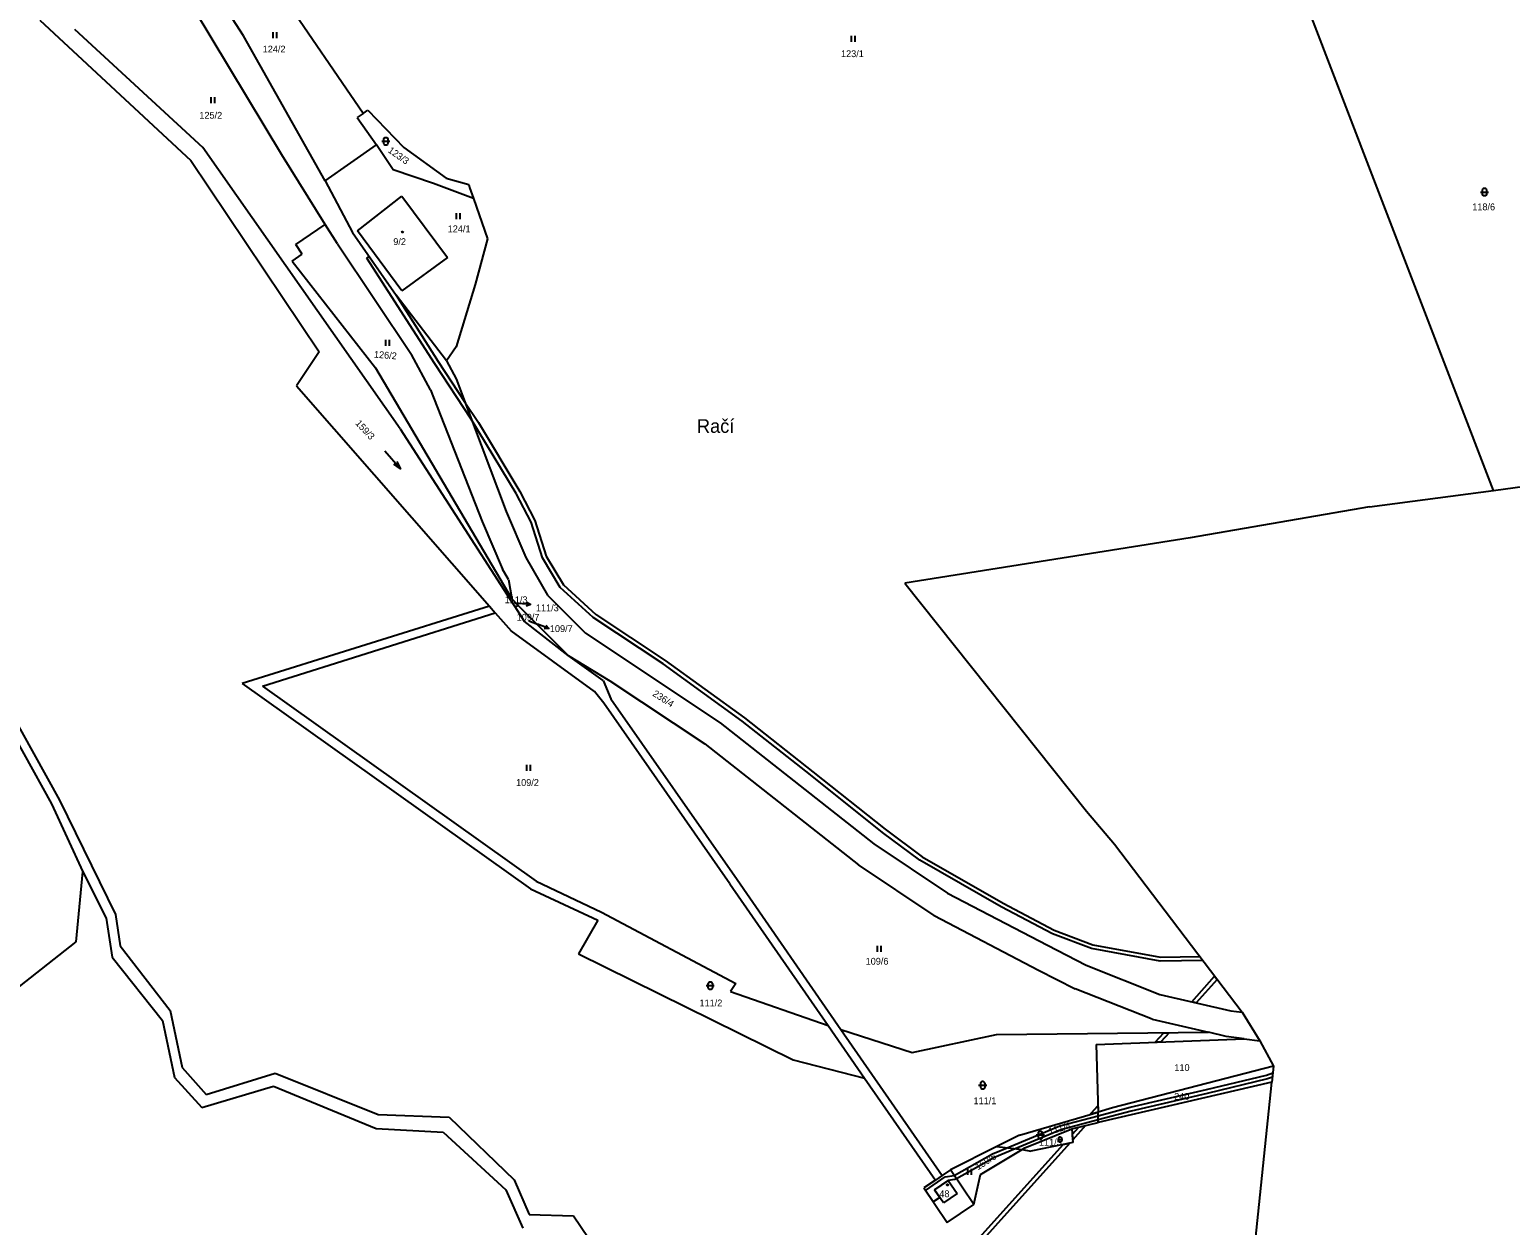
# Model space of a CAD drawing. Extents: x -811039 to -805820, y -1161436 to -1155864.
# Drawn here: x -809432.5 to -809063.2, y -1160199.3 to -1159901.1 of the extents above; entities that cross this region are included whole.
import ezdxf

# ---------------------------------------------------------------- set-up
doc = ezdxf.new("R2010")
doc.units = 0
for name, color, linetype in [('Default', 7, 'Continuous'), ('Hranice kat_území', 7, 'Continuous'), ('Hranice parcel', 7, 'Continuous'), ('Parcelní čísla', 7, 'Continuous'), ('Pop  PČ popisy', 7, 'Continuous'), ('Vnitřní kresba', 7, 'Continuous'), ('Věcná břemena k části', 7, 'Continuous'), ('Značky budov', 7, 'Continuous'), ('Značky kultur', 7, 'Continuous')]:
    doc.layers.add(name, color=color, linetype=linetype)

# ---------------------------------------------------------------- blocks, each defined once
blk = doc.blocks.new('306')
at = {"layer": 'Default'}
for p, q in [((-0.5, 1.5), (-0.5, 0)), ((0.5, 0), (0.5, 1.5))]:
    blk.add_line(p, q, dxfattribs=at)
blk = doc.blocks.new('316')
at = {"layer": 'Default'}
for points in [[(-1, 1), (0.27, 1), (1, 1)], [(-0.5, 1.5), (-0.4, 1.79), (-0.15, 1.97), (0.16, 1.97), (0.41, 1.79), (0.51, 1.5), (0.51, 0.5), (0.41, 0.21), (0.16, 0.03), (-0.15, 0.03), (-0.4, 0.21), (-0.5, 0.5), (-0.5, 1.5)]]:
    blk.add_lwpolyline(points, dxfattribs=at)
blk = doc.blocks.new('802')
at = {"layer": 'Default'}
blk.add_line((-3, 0), (3, 0), dxfattribs=at)
blk.add_lwpolyline([(1, 0.5), (3, 0), (1, -0.5)], dxfattribs=at)
blk = doc.blocks.new('10292')
at = {"layer": 'Default'}
blk.add_line((0, 3), (0, 0), dxfattribs=at)
blk.add_lwpolyline([(-0.5, 2), (0, 3), (0.5, 2)], dxfattribs=at)
blk = doc.blocks.new('402')
at = {"layer": 'Default'}
blk.add_lwpolyline([(0.09, 0.15), (0.18, 0), (0.09, -0.15), (-0.09, -0.15), (-0.18, 0), (-0.09, 0.15), (0.09, 0.15)], dxfattribs=at)

msp = doc.modelspace()

# ---------------------------------------------------------------- linework, layer by layer
at = {"layer": 'Hranice kat_území'}
for p, q in [((-809067.45, -1160016.03), (-809030.93, -1160011.2)), ((-809098.39, -1160020.11), (-809067.45, -1160016.03)), ((-809098.39, -1160020.11), (-809143.12, -1160027.89)), ((-809143.12, -1160027.89), (-809214.22, -1160039.19)), ((-809214.22, -1160039.19), (-809168.92, -1160096.04)), ((-809168.92, -1160096.04), (-809161.97, -1160104.28)), ((-809161.97, -1160104.28), (-809130.15, -1160146.17)), ((-809130.15, -1160146.17), (-809125.72, -1160153.31)), ((-809125.72, -1160153.31), (-809122.3, -1160159.64)), ((-809122.3, -1160159.64), (-809122.72, -1160163.6)), ((-809127.49, -1160209.16), (-809122.72, -1160163.6))]:
    msp.add_line(p, q, dxfattribs=at)
at = {"layer": 'Hranice parcel'}
for p, q in [((-809067.45, -1160016.03), (-809126.06, -1159863.64)), ((-809379.2, -1159902.71), (-809396.36, -1159875.89)), ((-809349.31, -1159922.05), (-809378.21, -1159879.76)), ((-809429.99, -1159898.77), (-809392.27, -1159933.76)), ((-809369.63, -1159932.33), (-809391.4, -1159896.21)), ((-809421.33, -1159901.04), (-809389.33, -1159930.55)), ((-809358.79, -1159938.85), (-809379.2, -1159902.71)), ((-809349.31, -1159922.05), (-809350.84, -1159923.07)), ((-809350.84, -1159923.07), (-809346, -1159929.89)), ((-809349.31, -1159922.05), (-809348.14, -1159921.26)), ((-809348.14, -1159921.26), (-809339.21, -1159930.5)), ((-809340.11, -1160000.67), (-809389.33, -1159930.55)), ((-809358.79, -1159938.85), (-809346, -1159929.89)), ((-809341.81, -1159936.08), (-809346, -1159929.89)), ((-809339.21, -1159930.5), (-809328.66, -1159938.21)), ((-809392.27, -1159933.76), (-809360.3, -1159981.53)), ((-809358.78, -1159949.7), (-809369.63, -1159932.33)), ((-809358.79, -1159938.85), (-809351.99, -1159951.73)), ((-809331.78, -1159939.48), (-809341.81, -1159936.08)), ((-809328.66, -1159938.21), (-809322.97, -1159939.79)), ((-809350.74, -1159951.29), (-809339.66, -1159942.68)), ((-809339.66, -1159942.68), (-809328.31, -1159957.96)), ((-809321.84, -1159943.27), (-809331.78, -1159939.48)), ((-809322.97, -1159939.79), (-809322.8, -1159940.55)), ((-809322.8, -1159940.55), (-809321.84, -1159943.27)), ((-809321.84, -1159943.27), (-809318.31, -1159953.35)), ((-809366.16, -1159954.76), (-809358.78, -1159949.7)), ((-809355.76, -1159954.53), (-809358.78, -1159949.7)), ((-809351.99, -1159951.73), (-809341.13, -1159967.36)), ((-809339.69, -1159966.3), (-809350.74, -1159951.29)), ((-809318.31, -1159953.35), (-809321.41, -1159964.66)), ((-809367.06, -1159958.87), (-809364.58, -1159957.1)), ((-809364.58, -1159957.1), (-809366.16, -1159954.76)), ((-809355.76, -1159954.53), (-809337.31, -1159982.17)), ((-809367.06, -1159958.87), (-809346.28, -1159985.44)), ((-809328.31, -1159957.96), (-809339.69, -1159966.3)), ((-809321.41, -1159964.66), (-809326.16, -1159980.21)), ((-809328.54, -1159983.73), (-809341.13, -1159967.36)), ((-809360.3, -1159981.53), (-809365.93, -1159989.95)), ((-809332.58, -1159990.98), (-809337.31, -1159982.17)), ((-809326.16, -1159980.21), (-809328.54, -1159983.73)), ((-809328.54, -1159983.73), (-809326.14, -1159988.22)), ((-809346.28, -1159985.44), (-809312.23, -1160043.12)), ((-809365.93, -1159989.95), (-809317.85, -1160044.93)), ((-809332.58, -1159990.98), (-809319.69, -1160023.76)), ((-809326.14, -1159988.22), (-809313.66, -1160021.34)), ((-809340.11, -1160000.67), (-809312.66, -1160043.26)), ((-809319.69, -1160023.76), (-809314.59, -1160035.71)), ((-809313.66, -1160021.34), (-809308.76, -1160032.8)), ((-809308.76, -1160032.8), (-809303.34, -1160042.21)), ((-809313.12, -1160038.25), (-809314.59, -1160035.71)), ((-809313.12, -1160038.25), (-809312.23, -1160043.12)), ((-809303.34, -1160042.21), (-809293.85, -1160051.68)), ((-809454.13, -1160045.44), (-809427.07, -1160094.22)), ((-809451.73, -1160045.3), (-809425.03, -1160093.32)), ((-809317.85, -1160044.93), (-809379.47, -1160064.19)), ((-809317.85, -1160044.93), (-809316.42, -1160046.57)), ((-809312.23, -1160043.12), (-809312.66, -1160043.26)), ((-809312.66, -1160043.26), (-809311.54, -1160045)), ((-809312.23, -1160043.12), (-809310.66, -1160044.72)), ((-809311.54, -1160045), (-809310.66, -1160044.72)), ((-809311.54, -1160045), (-809309.2, -1160048.63)), ((-809310.66, -1160044.72), (-809298.21, -1160057.19)), ((-809374.46, -1160064.84), (-809316.42, -1160046.57)), ((-809316.42, -1160046.57), (-809312.45, -1160051.1)), ((-809298.21, -1160057.19), (-809309.2, -1160048.63)), ((-809291.62, -1160066.18), (-809312.45, -1160051.1)), ((-809293.85, -1160051.68), (-809260.32, -1160073.99)), ((-809289.45, -1160063.43), (-809298.21, -1160057.19)), ((-809298.21, -1160057.19), (-809287.8, -1160063.51)), ((-809379.47, -1160064.19), (-809307.59, -1160115.43)), ((-809374.46, -1160064.84), (-809306.19, -1160113.52)), ((-809289.45, -1160063.43), (-809287.56, -1160068.04)), ((-809287.8, -1160063.51), (-809264.14, -1160079.26)), ((-809289.32, -1160069.08), (-809291.62, -1160066.18)), ((-809287.56, -1160068.04), (-809256.06, -1160113.07)), ((-809257.89, -1160114.17), (-809289.32, -1160069.08)), ((-809260.32, -1160073.99), (-809221.98, -1160104.19)), ((-809264.14, -1160079.26), (-809225.8, -1160109.45)), ((-809427.07, -1160094.22), (-809419.25, -1160111.18)), ((-809425.03, -1160093.32), (-809411.06, -1160121.78)), ((-809221.98, -1160104.19), (-809203.63, -1160116.46)), ((-809420.88, -1160128.61), (-809419.25, -1160111.18)), ((-809419.25, -1160111.18), (-809413.46, -1160122.7)), ((-809206.95, -1160122.06), (-809225.8, -1160109.45)), ((-809307.59, -1160115.43), (-809290.84, -1160123.22)), ((-809306.19, -1160113.52), (-809289.91, -1160121.2)), ((-809257.89, -1160114.17), (-809233.37, -1160149.5)), ((-809256.06, -1160113.07), (-809230.18, -1160150.48)), ((-809203.63, -1160116.46), (-809178.69, -1160129.43)), ((-809413.46, -1160122.7), (-809411.9, -1160132.48)), ((-809411.06, -1160121.78), (-809409.97, -1160129.58)), ((-809290.84, -1160123.22), (-809295.61, -1160131.62)), ((-809289.91, -1160121.2), (-809256.39, -1160139)), ((-809206.95, -1160122.06), (-809180.93, -1160135.68)), ((-809435.03, -1160139.74), (-809420.88, -1160128.61)), ((-809409.97, -1160129.58), (-809397.42, -1160145.71)), ((-809178.69, -1160129.43), (-809169.07, -1160134.44)), ((-809411.9, -1160132.48), (-809399.36, -1160148.23)), ((-809295.61, -1160131.62), (-809242.1, -1160158.08)), ((-809169.07, -1160134.44), (-809150.64, -1160141.71)), ((-809180.93, -1160135.68), (-809171.75, -1160140.37)), ((-809256.39, -1160139), (-809257.74, -1160141.04)), ((-809257.74, -1160141.04), (-809233.37, -1160149.5)), ((-809152.58, -1160147.93), (-809171.75, -1160140.37)), ((-809150.64, -1160141.71), (-809132.98, -1160145.8)), ((-809397.42, -1160145.71), (-809394.46, -1160159.95)), ((-809132.98, -1160145.8), (-809130.15, -1160146.17)), ((-809399.36, -1160148.23), (-809396.35, -1160162.42)), ((-809233.37, -1160149.5), (-809224.27, -1160162.61)), ((-809152.58, -1160147.93), (-809138.55, -1160151.18)), ((-809230.18, -1160150.48), (-809204.97, -1160186.92)), ((-809230.18, -1160150.48), (-809212.41, -1160156.18)), ((-809212.41, -1160156.18), (-809191.36, -1160151.76)), ((-809191.36, -1160151.76), (-809138.55, -1160151.18)), ((-809166.53, -1160154.18), (-809129.63, -1160152.79)), ((-809134.14, -1160152.2), (-809138.55, -1160151.18)), ((-809129.63, -1160152.79), (-809134.14, -1160152.2)), ((-809129.63, -1160152.79), (-809125.72, -1160153.31)), ((-809166.53, -1160154.18), (-809166.07, -1160171.09)), ((-809394.46, -1160159.95), (-809388.49, -1160166.65)), ((-809242.1, -1160158.08), (-809224.27, -1160162.61)), ((-809122.3, -1160159.64), (-809162.45, -1160170.03)), ((-809396.35, -1160162.42), (-809389.58, -1160169.92)), ((-809389.58, -1160169.92), (-809371.71, -1160164.62)), ((-809388.49, -1160166.65), (-809371.31, -1160161.36)), ((-809371.71, -1160164.62), (-809346.09, -1160175.15)), ((-809371.31, -1160161.36), (-809345.55, -1160171.68)), ((-809224.27, -1160162.61), (-809206.63, -1160188.04)), ((-809122.72, -1160163.6), (-809166, -1160173.7)), ((-809345.55, -1160171.68), (-809327.88, -1160172.36)), ((-809185.67, -1160176.82), (-809166.07, -1160171.09)), ((-809162.45, -1160170.03), (-809166.07, -1160171.09)), ((-809166, -1160173.7), (-809166.07, -1160171.09)), ((-809346.09, -1160175.15), (-809329.35, -1160176.05)), ((-809327.88, -1160172.36), (-809311.71, -1160187.99)), ((-809184.32, -1160180.02), (-809172.57, -1160175.23)), ((-809172.57, -1160175.23), (-809166, -1160173.7)), ((-809172.57, -1160175.23), (-809172.35, -1160178.68)), ((-809329.35, -1160176.05), (-809313.76, -1160190.44)), ((-809185.67, -1160176.82), (-809191.29, -1160179.65)), ((-809172.35, -1160178.68), (-809182.82, -1160180.81)), ((-809191.29, -1160179.65), (-809202.88, -1160185.49)), ((-809195.4, -1160186.64), (-809185.01, -1160180.43)), ((-809191.29, -1160179.65), (-809185.01, -1160180.43)), ((-809185.01, -1160180.43), (-809184.32, -1160180.02)), ((-809185.01, -1160180.43), (-809182.82, -1160180.81)), ((-809202.88, -1160185.49), (-809204.97, -1160186.92)), ((-809197.03, -1160194.09), (-809202.88, -1160185.49)), ((-809197.03, -1160194.09), (-809195.4, -1160186.64)), ((-809313.76, -1160190.44), (-809309.52, -1160200.03)), ((-809311.71, -1160187.99), (-809307.91, -1160196.57)), ((-809206.63, -1160188.04), (-809209.52, -1160190)), ((-809209.52, -1160190), (-809203.71, -1160198.62)), ((-809204.97, -1160186.92), (-809206.63, -1160188.04)), ((-809203.71, -1160198.62), (-809197.03, -1160194.09)), ((-809307.91, -1160196.57), (-809296.85, -1160196.95)), ((-809296.85, -1160196.95), (-809285.9, -1160213.07))]:
    msp.add_line(p, q, dxfattribs=at)
at = {"layer": 'Pop  PČ popisy'}
for p, q in [((-809311.56, -1160044.17), (-809310.63, -1160044.24)), ((-809307.99, -1160048.53), (-809305.85, -1160049.36))]:
    msp.add_line(p, q, dxfattribs=at)
at = {"layer": 'Vnitřní kresba'}
for p, q in [((-809206.86, -1160190.44), (-809203.43, -1160188.17)), ((-809204.64, -1160193.7), (-809206.86, -1160190.44)), ((-809203.43, -1160188.17), (-809201.24, -1160191.34)), ((-809201.24, -1160191.34), (-809204.64, -1160193.7))]:
    msp.add_line(p, q, dxfattribs=at)
at = {"layer": 'Věcná břemena k části'}
for p, q in [((-809348.44, -1159958.12), (-809347.85, -1159957.68)), ((-809347.85, -1159957.68), (-809341.13, -1159967.36)), ((-809331.5, -1159984.48), (-809348.44, -1159958.12)), ((-809341.13, -1159967.36), (-809330.66, -1159983.94)), ((-809322.36, -1159998.25), (-809331.5, -1159984.48)), ((-809330.66, -1159983.94), (-809323.94, -1159994.07)), ((-809323.94, -1159994.07), (-809320.61, -1159999.08)), ((-809311.14, -1160016.81), (-809322.36, -1159998.25)), ((-809320.61, -1159999.08), (-809310.26, -1160016.33)), ((-809307.42, -1160023.95), (-809311.14, -1160016.81)), ((-809310.26, -1160016.33), (-809306.5, -1160023.57)), ((-809304.59, -1160032.9), (-809307.42, -1160023.95)), ((-809306.5, -1160023.57), (-809303.67, -1160032.48)), ((-809300.19, -1160040.23), (-809304.59, -1160032.9)), ((-809303.67, -1160032.48), (-809299.41, -1160039.59)), ((-809291.96, -1160047.78), (-809300.19, -1160040.23)), ((-809299.41, -1160039.59), (-809291.34, -1160046.98)), ((-809274.55, -1160059.28), (-809291.96, -1160047.78)), ((-809291.34, -1160046.98), (-809273.99, -1160058.46)), ((-809254.8, -1160073.56), (-809274.55, -1160059.28)), ((-809273.99, -1160058.46), (-809254.2, -1160072.76)), ((-809237.79, -1160086.97), (-809254.8, -1160073.56)), ((-809254.2, -1160072.76), (-809237.17, -1160086.19)), ((-809219.79, -1160101.36), (-809237.79, -1160086.97)), ((-809237.17, -1160086.19), (-809219.19, -1160100.56)), ((-809210.49, -1160108.22), (-809219.79, -1160101.36)), ((-809219.19, -1160100.56), (-809209.95, -1160107.38)), ((-809190.25, -1160119.87), (-809210.49, -1160108.22)), ((-809209.95, -1160107.38), (-809189.77, -1160118.99)), ((-809177.44, -1160126.6), (-809190.25, -1160119.87)), ((-809189.77, -1160118.99), (-809177.02, -1160125.68)), ((-809167.69, -1160130.32), (-809177.44, -1160126.6)), ((-809177.02, -1160125.68), (-809167.41, -1160129.36)), ((-809150.59, -1160133.46), (-809167.69, -1160130.32)), ((-809167.41, -1160129.36), (-809150.51, -1160132.46)), ((-809139.95, -1160133.27), (-809150.59, -1160133.46)), ((-809150.51, -1160132.46), (-809140.7, -1160132.29)), ((-809139.04, -1160165.45), (-809124.06, -1160161.84)), ((-809123.78, -1160162.8), (-809138.82, -1160166.43)), ((-809124.06, -1160161.84), (-809122.47, -1160161.28)), ((-809122.59, -1160162.38), (-809123.78, -1160162.8)), ((-809158.06, -1160169.84), (-809139.04, -1160165.45)), ((-809138.82, -1160166.43), (-809157.82, -1160170.82)), ((-809175.63, -1160174.52), (-809166.05, -1160171.97)), ((-809166.05, -1160171.97), (-809158.06, -1160169.84)), ((-809157.82, -1160170.82), (-809166.02, -1160173)), ((-809188.74, -1160179.97), (-809175.63, -1160174.52)), ((-809175.31, -1160175.46), (-809186.74, -1160180.22)), ((-809166.02, -1160173), (-809175.31, -1160175.46)), ((-809201.96, -1160186.85), (-809192.36, -1160181.47)), ((-809191.92, -1160182.37), (-809201.39, -1160187.68)), ((-809192.36, -1160181.47), (-809188.74, -1160179.97)), ((-809186.74, -1160180.22), (-809191.92, -1160182.37)), ((-809209.08, -1160190.65), (-809204.18, -1160187.23)), ((-809203.43, -1160188.17), (-809206.86, -1160190.44)), ((-809206.86, -1160190.44), (-809205.52, -1160192.4)), ((-809204.18, -1160187.23), (-809201.96, -1160186.85)), ((-809201.81, -1160187.91), (-809203.43, -1160188.17)), ((-809201.39, -1160187.68), (-809201.81, -1160187.91)), ((-809207.2, -1160193.45), (-809209.08, -1160190.65)), ((-809205.52, -1160192.4), (-809207.2, -1160193.45))]:
    msp.add_line(p, q, dxfattribs=at)
for points in [[(-809142.72, -1160143.54), (-809136.99, -1160137.17), (-809136.37, -1160137.98), (-809141.61, -1160143.8)], [(-809151.79, -1160153.62), (-809149.7, -1160151.3), (-809148.35, -1160151.29), (-809150.4, -1160153.57)], [(-809168.02, -1160171.66), (-809167.68, -1160171.28), (-809166.11, -1160169.54), (-809166.08, -1160170.77), (-809166.07, -1160171.09)], [(-809172.48, -1160176.62), (-809170.88, -1160174.84), (-809169.19, -1160174.45), (-809172.39, -1160178.01)], [(-809229.94, -1160240.51), (-809174.78, -1160179.17), (-809173.13, -1160178.84), (-809228.96, -1160240.92)]]:
    msp.add_lwpolyline(points, close=True, dxfattribs=at)

# ---------------------------------------------------------------- block references
at = {"layer": 'Pop  PČ popisy'}
for p, rotation in [((-809310.63, -1160044.24), -94.548654), ((-809305.85, -1160049.36), -111.27902100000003)]:
    msp.add_blockref('10292', p, dxfattribs=dict(at, rotation=rotation))
at = {"layer": 'Značky budov'}
for p in [(-809339.51, -1159951.62), (-809203.64, -1160189.2)]:
    msp.add_blockref('402', p, dxfattribs=at)
at = {"layer": 'Značky kultur'}
for name, p in [('306', (-809371.36, -1159903.29)), ('306', (-809227.12, -1159904.19)), ('306', (-809386.81, -1159919.51)), ('316', (-809343.69, -1159929.98)), ('316', (-809069.73, -1159942.64)), ('306', (-809325.65, -1159948.42)), ('306', (-809343.3, -1159980.02)), ('306', (-809308.08, -1160086)), ('306', (-809220.67, -1160131.14)), ('316', (-809262.76, -1160140.54)), ('316', (-809194.84, -1160165.37)), ('316', (-809180.46, -1160177.76)), ('306', (-809198.13, -1160186.7))]:
    msp.add_blockref(name, p, dxfattribs=at)
at = {"layer": 'Značky kultur', "rotation": -49.05580499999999}
msp.add_blockref('802', (-809342, -1160008.42), dxfattribs=at)
at = {"layer": 'Značky kultur', "xscale": 0.67, "yscale": 0.67}
msp.add_blockref('316', (-809175.55, -1160178.58), dxfattribs=at)

# ---------------------------------------------------------------- texts
at = {"layer": 'Parcelní čísla'}
for s, p in [('124/2', (-809374.38, -1159906.84)), ('123/1', (-809230.16, -1159908)), ('125/2', (-809390.18, -1159923.35)), ('118/6', (-809072.75, -1159946.19)), ('124/1', (-809328.25, -1159951.67)), ('9/2', (-809341.82, -1159954.86)), ('111/3', (-809314.04, -1160044.17)), ('111/3', (-809306.25, -1160046.18)), ('109/7', (-809311.06, -1160048.53)), ('109/7', (-809302.77, -1160051.37)), ('109/2', (-809311.2, -1160089.74)), ('109/6', (-809224.03, -1160134.31)), ('111/2', (-809265.46, -1160144.71)), ('110', (-809147.03, -1160160.83)), ('111/1', (-809197.12, -1160169.11)), ('240', (-809147.09, -1160168.01)), ('111/5', (-809180.81, -1160179.43)), ('48', (-809205.65, -1160192.29))]:
    msp.add_text(s, height=1.7, dxfattribs=at).set_placement(p)
for s, rotation, p in [('123/3', 324.924, (-809343.3, -1159931.6)), ('126/2', 355.463, (-809346.69, -1159982.93)), ('159/3', 312.663, (-809351.4, -1159999.41)), ('236/4', 327.102, (-809277.31, -1160067.14)), ('111/4', 16.157, (-809178.18, -1160176.73)), ('159/5', 32.487, (-809196.02, -1160185.63))]:
    msp.add_text(s, height=1.7, rotation=rotation, dxfattribs=at).set_placement(p)
at = {"layer": 'Pop  PČ popisy'}
msp.add_text('Račí', height=3.4, dxfattribs=at).set_placement((-809266.11, -1160001.69))

doc.saveas('drawing.dxf')
